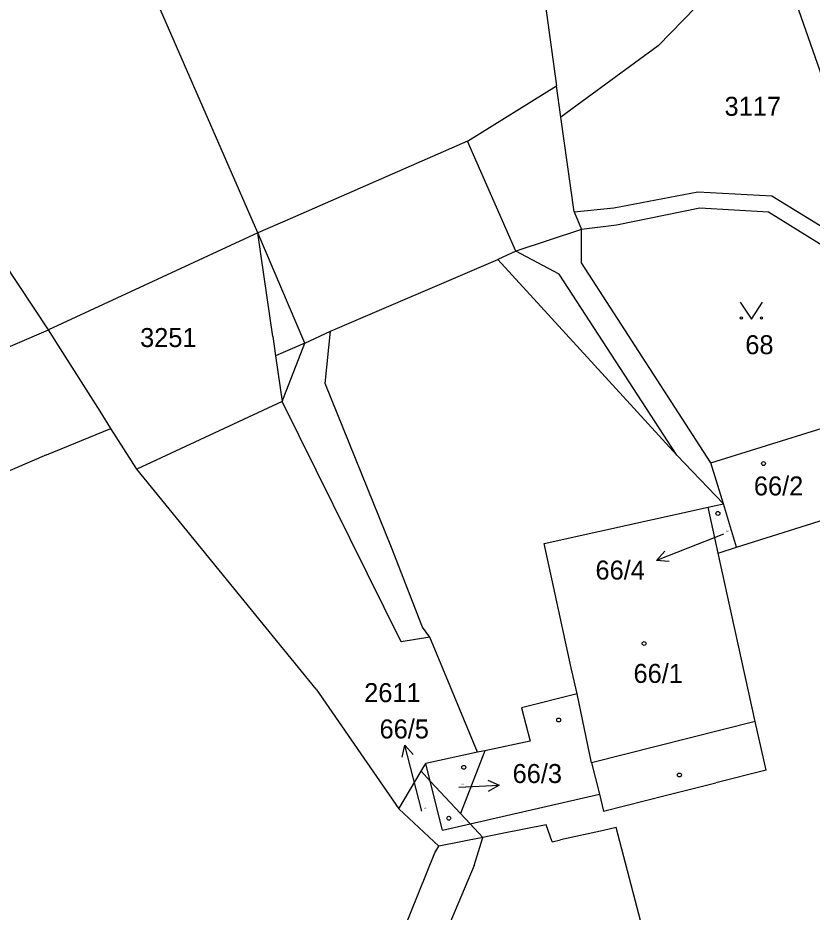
# Model space of a CAD drawing. Extents: x -736345 to -729997, y -1130177 to -1122501.
# Drawn here: x -733843 to -733771.8, y -1126528.3 to -1126448.2 of the extents above; entities that cross this region are included whole.
import ezdxf

# ---------------------------------------------------------------- set-up
doc = ezdxf.new("R2010")
doc.units = 0
for name, color, linetype in [('Vrstva 1', 7, 'Continuous'), ('Vrstva 16', 7, 'Continuous'), ('Vrstva 18', 7, 'Continuous'), ('Vrstva 19', 7, 'Continuous'), ('Vrstva 25', 7, 'Continuous'), ('Vrstva 4', 7, 'Continuous')]:
    doc.layers.add(name, color=color, linetype=linetype)

msp = doc.modelspace()

# ---------------------------------------------------------------- linework, layer by layer
at = {"layer": 'Vrstva 1'}
for points in [[(-733763.65, -1126474.3), (-733777.81, -1126433.87)], [(-733821.47, -1126467.45), (-733831.32, -1126444.86)], [(-733796.06, -1126444.51), (-733794.72, -1126454.29)], [(-733782.28, -1126447.28), (-733785.63, -1126450.72)], [(-733840.23, -1126476.13), (-733857.59, -1126449.95)], [(-733785.63, -1126450.72), (-733791.97, -1126455.37)], [(-733794.33, -1126457.1), (-733794.72, -1126454.29)], [(-733791.97, -1126455.37), (-733794.33, -1126457.1)], [(-733793.16, -1126465.59), (-733794.33, -1126457.1)], [(-733789.58, -1126465.21), (-733782.06, -1126463.78)], [(-733782.06, -1126463.78), (-733775.43, -1126464.13)], [(-733775.43, -1126464.13), (-733769.41, -1126467.85)], [(-733793.16, -1126465.59), (-733789.58, -1126465.21)], [(-733793.16, -1126465.59), (-733792.48, -1126467.16)], [(-733781.88, -1126465.26), (-733789.34, -1126466.78)], [(-733775.73, -1126465.62), (-733781.88, -1126465.26)], [(-733770.54, -1126468.84), (-733775.73, -1126465.62)], [(-733821.47, -1126467.45), (-733840.23, -1126476.13)], [(-733821.17, -1126469.55), (-733821.47, -1126467.45)], [(-733792.49, -1126470.14), (-733792.48, -1126467.16)], [(-733789.34, -1126466.78), (-733792.48, -1126467.16)], [(-733820.13, -1126476.73), (-733821.17, -1126469.55)], [(-733780.9, -1126488.05), (-733792.49, -1126470.14)], [(-733839.36, -1126477.51), (-733840.23, -1126476.13)], [(-733820.13, -1126476.73), (-733819.88, -1126478.48)], [(-733835.61, -1126483.42), (-733839.36, -1126477.51)], [(-733819.88, -1126478.48), (-733819.29, -1126482.56)], [(-733819.29, -1126482.56), (-733832.31, -1126488.62)], [(-733808.65, -1126504.07), (-733819.29, -1126482.56)], [(-733834.63, -1126484.97), (-733835.61, -1126483.42)], [(-733832.31, -1126488.62), (-733834.63, -1126484.97)], [(-733780.9, -1126488.05), (-733770.93, -1126484.93)], [(-733779.78, -1126491.72), (-733780.9, -1126488.05)], [(-733816.25, -1126508.3), (-733832.31, -1126488.62)], [(-733795.82, -1126495.27), (-733781.15, -1126492.02)], [(-733781.15, -1126492.02), (-733779.78, -1126491.72)], [(-733780.25, -1126496.12), (-733781.15, -1126492.02)], [(-733778.6, -1126495.6), (-733779.78, -1126491.72)], [(-733778.6, -1126495.6), (-733768.56, -1126492.44)], [(-733793.4, -1126506.38), (-733795.82, -1126495.27)], [(-733780.25, -1126496.12), (-733778.6, -1126495.6)], [(-733806.08, -1126503.66), (-733808.65, -1126504.07)], [(-733804.26, -1126508.03), (-733806.08, -1126503.66)], [(-733792.88, -1126508.72), (-733793.4, -1126506.38)], [(-733816.25, -1126508.3), (-733808.85, -1126519)], [(-733801.79, -1126513.95), (-733804.26, -1126508.03)], [(-733792.88, -1126508.72), (-733797.86, -1126509.96)], [(-733797.86, -1126509.96), (-733797.1, -1126512.94)], [(-733797.1, -1126512.94), (-733801.15, -1126513.81)], [(-733801.15, -1126513.81), (-733803.33, -1126519.43)], [(-733801.15, -1126513.81), (-733801.79, -1126513.95)], [(-733801.79, -1126513.95), (-733806.43, -1126514.95)], [(-733806.85, -1126515.65), (-733806.43, -1126514.95)], [(-733808.85, -1126519), (-733806.85, -1126515.65)], [(-733806.04, -1126516.52), (-733806.85, -1126515.65)], [(-733803.33, -1126519.43), (-733806.04, -1126516.52)], [(-733805.26, -1126522.35), (-733808.85, -1126519)], [(-733802.47, -1126520.36), (-733803.33, -1126519.43)], [(-733801.33, -1126521.57), (-733802.47, -1126520.36)], [(-733795.66, -1126520.44), (-733799.75, -1126521.26)], [(-733795.12, -1126521.96), (-733795.66, -1126520.44)], [(-733790.53, -1126520.95), (-733794.38, -1126521.8)], [(-733789.39, -1126520.69), (-733790.53, -1126520.95)], [(-733785.51, -1126535.51), (-733789.39, -1126520.69)], [(-733801.33, -1126521.57), (-733805.26, -1126522.35)], [(-733799.75, -1126521.26), (-733801.33, -1126521.57)], [(-733795.12, -1126521.96), (-733794.38, -1126521.8)]]:
    msp.add_lwpolyline(points, dxfattribs=at)
at = {"layer": 'Vrstva 16'}
for points in [[(-733779.76, -1126494.42), (-733782.97, -1126495.69)], [(-733806.79, -1126519.21), (-733807.56, -1126516.21)], [(-733803.46, -1126517.07), (-733802.86, -1126517.04)]]:
    msp.add_lwpolyline(points, dxfattribs=at)
at = {"layer": 'Vrstva 25'}
for points in [[(-733778.27, -1126473.67), (-733777.27, -1126475.17), (-733776.27, -1126473.67)], [(-733782.97, -1126495.69), (-733785.761, -1126496.789)], [(-733784.647, -1126496.888), (-733785.761, -1126496.789), (-733785.014, -1126495.957)], [(-733808.541, -1126514.398), (-733808.306, -1126513.305), (-733807.573, -1126514.149)], [(-733807.56, -1126516.21), (-733808.306, -1126513.305)], [(-733802.86, -1126517.04), (-733799.864, -1126516.899)], [(-733800.886, -1126516.447), (-733799.864, -1126516.899), (-733800.839, -1126517.445)]]:
    msp.add_lwpolyline(points, dxfattribs=at)
for centre, radius in [((-733778.17, -1126475.07), 0.1), ((-733776.37, -1126475.07), 0.1), ((-733776.19, -1126488.11), 0.175), ((-733780.27, -1126492.57), 0.175), ((-733786.88, -1126504.21), 0.175), ((-733794.53, -1126511.06), 0.175), ((-733803.03, -1126515.3), 0.175), ((-733783.72, -1126515.98), 0.175), ((-733804.37, -1126519.85), 0.175)]:
    msp.add_circle(centre, radius, dxfattribs=at)
at = {"layer": 'Vrstva 4'}
for points in [[(-733802.71, -1126459.24), (-733794.72, -1126454.29)], [(-733802.71, -1126459.24), (-733818.59, -1126466.19)], [(-733798.36, -1126469.11), (-733802.71, -1126459.24)], [(-733818.59, -1126466.19), (-733821.47, -1126467.45)], [(-733817.28, -1126477.34), (-733821.47, -1126467.45)], [(-733792.48, -1126467.16), (-733798.36, -1126469.11)], [(-733814.98, -1126476.26), (-733799.98, -1126469.83)], [(-733798.36, -1126469.11), (-733799.98, -1126469.83)], [(-733799.98, -1126469.83), (-733783.96, -1126487.36)], [(-733794.48, -1126471.16), (-733798.36, -1126469.11)], [(-733783.96, -1126487.36), (-733794.48, -1126471.16)], [(-733846.42, -1126478.8), (-733840.23, -1126476.13)], [(-733817.28, -1126477.34), (-733814.98, -1126476.26)], [(-733815.44, -1126480.94), (-733814.98, -1126476.26)], [(-733817.28, -1126477.34), (-733819.88, -1126478.48)], [(-733819.29, -1126482.56), (-733817.28, -1126477.34)], [(-733809.5, -1126495.63), (-733815.44, -1126480.94)], [(-733840.39, -1126487.32), (-733834.63, -1126484.97)], [(-733840.39, -1126487.32), (-733895.37, -1126511.02)], [(-733783.96, -1126487.36), (-733779.78, -1126491.72)], [(-733806.72, -1126502.74), (-733809.5, -1126495.63)], [(-733776.94, -1126511.2), (-733780.25, -1126496.12)], [(-733806.08, -1126503.66), (-733806.72, -1126502.74)], [(-733791.59, -1126514.9), (-733792.88, -1126508.72)], [(-733776.94, -1126511.2), (-733791.59, -1126514.9)], [(-733775.95, -1126515.56), (-733776.94, -1126511.2)], [(-733806.04, -1126516.52), (-733806.43, -1126514.95)], [(-733791.59, -1126514.9), (-733790.87, -1126517.71)], [(-733775.95, -1126515.56), (-733780.45, -1126516.68)], [(-733804.94, -1126520.92), (-733806.04, -1126516.52)], [(-733784.87, -1126517.79), (-733780.45, -1126516.68)], [(-733802.47, -1126520.36), (-733790.87, -1126517.71)], [(-733790.87, -1126517.71), (-733790.53, -1126519.22)], [(-733790.53, -1126519.22), (-733784.87, -1126517.79)], [(-733804.94, -1126520.92), (-733802.47, -1126520.36)], [(-733802.11, -1126524.09), (-733801.33, -1126521.57)], [(-733805.63, -1126522.96), (-733805.26, -1126522.35)], [(-733818.4, -1126554.6), (-733805.63, -1126522.96)], [(-733802.11, -1126524.09), (-733815.96, -1126556.86)]]:
    msp.add_lwpolyline(points, dxfattribs=at)

# ---------------------------------------------------------------- texts
at = {"layer": 'Vrstva 16'}
for s, p in [('66/4', (-733791.236, -1126498.49)), ('66/5', (-733810.576, -1126512.71)), ('66/3', (-733798.66, -1126516.7))]:
    msp.add_text(s, height=1.7, dxfattribs=at).set_placement(p)
at = {"layer": 'Vrstva 18'}
for s, p in [('3117', (-733779.68, -1126456.98)), ('3251', (-733832.02, -1126477.68)), ('68', (-733777.82, -1126478.32)), ('2611', (-733811.95, -1126509.46))]:
    msp.add_text(s, height=1.7, dxfattribs=at).set_placement(p)
at = {"layer": 'Vrstva 19'}
for s, height, p in [('66/2', 1.7, (-733777.05, -1126490.96)), ('66/4', 0.1, (-733779.56, -1126494.22)), ('66/1', 1.7, (-733787.83, -1126507.74)), ('66/3', 0.1, (-733803.26, -1126516.87)), ('66/5', 0.1, (-733806.59, -1126519.01))]:
    msp.add_text(s, height=height, dxfattribs=at).set_placement(p)

doc.saveas('drawing.dxf')
